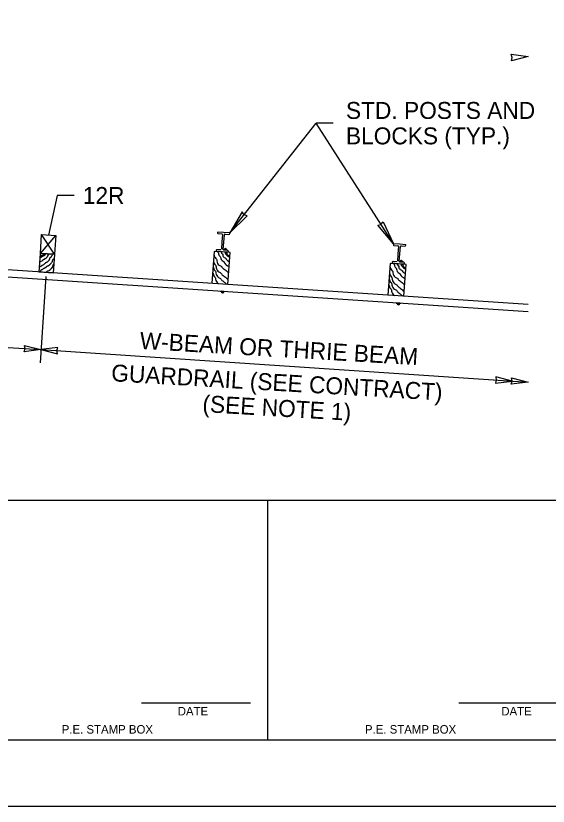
# Model space of a CAD drawing. Extents: x 1312564.2 to 1312581.5, y 1207298.4 to 1207352.6.
# Drawn here: x 1312573.115 to 1312575.615, y 1207298.421 to 1207302.136 of the extents above; entities that cross this region are included whole.
import ezdxf

# ---------------------------------------------------------------- set-up
doc = ezdxf.new("R2010")
doc.units = 0
for name, color, linetype in [('Level 1', 7, 'Continuous'), ('Level 10', 7, 'Continuous'), ('Level 13', 7, 'Continuous'), ('Level 14', 7, 'Continuous'), ('Level 15', 7, 'Continuous'), ('Level 2', 7, 'Continuous'), ('Level 20', 7, 'Continuous'), ('Level 3', 7, 'Continuous'), ('Level 36', 7, 'Continuous'), ('Level 9', 7, 'Continuous'), ('SH_GI_SheetTextInCells', 7, 'Continuous')]:
    doc.layers.add(name, color=color, linetype=linetype)

msp = doc.modelspace()

# ---------------------------------------------------------------- linework, layer by layer
at = {"layer": 'Level 1'}
for p, q in [((1312565.4154872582, 1207299.8593171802), (1312581.1654872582, 1207299.8593171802)), ((1312574.2982728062, 1207298.7334171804), (1312574.2982728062, 1207299.8593171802)), ((1312573.7057800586, 1207298.9067231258), (1312574.2175066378, 1207298.9067231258)), ((1312575.1952105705, 1207298.9067231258), (1312575.7069371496, 1207298.9067231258)), ((1312565.4154872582, 1207298.7334171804), (1312581.1654872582, 1207298.7334171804))]:
    msp.add_line(p, q, dxfattribs=at)
at = {"layer": 'Level 10'}
for p, q in [((1312574.0461583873, 1207301.0279184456), (1312574.0358822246, 1207300.8786255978)), ((1312574.1207275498, 1207301.022785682), (1312574.0461583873, 1207301.0279184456)), ((1312574.1104556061, 1207300.873554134), (1312574.1207275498, 1207301.022785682)), ((1312574.8727631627, 1207300.9721786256), (1312574.862487, 1207300.8228857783)), ((1312574.9473323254, 1207300.9670458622), (1312574.8727631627, 1207300.9721786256)), ((1312574.9370603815, 1207300.8178143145), (1312574.9473323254, 1207300.9670458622))]:
    msp.add_line(p, q, dxfattribs=at)
at = {"layer": 'Level 13'}
for points in [[(1312573.294965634, 1207300.9975759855), (1312573.2905538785, 1207300.9911023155), (1312573.2898937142, 1207300.9904370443), (1312573.2890815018, 1207300.9899128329), (1312573.2882636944, 1207300.9893941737), (1312573.2875867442, 1207300.9887455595), (1312573.2870264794, 1207300.9878017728), (1312573.2866269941, 1207300.9867753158), (1312573.2861106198, 1207300.9845726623), (1312573.2856381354, 1207300.982334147), (1312573.2850722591, 1207300.980749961), (1312573.2848100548, 1207300.9802563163), (1312573.2817499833, 1207300.9753688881), (1312573.2783825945, 1207300.97070553), (1312573.2746248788, 1207300.9663347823), (1312573.2725737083, 1207300.964280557), (1312573.271500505, 1207300.9632899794), (1312573.2703938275, 1207300.9623251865), (1312573.268983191, 1207300.9613166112), (1312573.267453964, 1207300.9605123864), (1312573.264204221, 1207300.95925536), (1312573.2609735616, 1207300.9580308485), (1312573.258760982, 1207300.9568190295), (1312573.258090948, 1207300.9563155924), (1312573.257372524, 1207300.9555539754), (1312573.256746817, 1207300.954677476), (1312573.256101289, 1207300.9538213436), (1312573.2553234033, 1207300.9531208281), (1312573.2515998, 1207300.9508374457), (1312573.2477912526, 1207300.9486758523), (1312573.243992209, 1207300.946494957), (1312573.2402971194, 1207300.9441536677), (1312573.2246592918, 1207300.933465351)], [(1312573.2881720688, 1207301.0155702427), (1312573.2850821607, 1207301.010632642), (1312573.2832165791, 1207301.0077283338), (1312573.2812929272, 1207301.0048604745), (1312573.2793293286, 1207301.0020213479), (1312573.2773439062, 1207300.9992032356), (1312573.2770386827, 1207300.9988782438), (1312573.276663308, 1207300.9986283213), (1312573.2757935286, 1207300.9982558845), (1312573.274917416, 1207300.9978903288), (1312573.2742178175, 1207300.9973360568), (1312573.273876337, 1207300.9968408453), (1312573.273586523, 1207300.9963166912), (1312573.2731335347, 1207300.99519701), (1312573.2725355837, 1207300.9927803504), (1312573.2719701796, 1207300.9903333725), (1312573.271294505, 1207300.988627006), (1312573.270983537, 1207300.9881033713), (1312573.2692403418, 1207300.9856209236), (1312573.2673483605, 1207300.9832459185), (1312573.2652962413, 1207300.9809995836), (1312573.2630726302, 1207300.978903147), (1312573.2619236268, 1207300.9780602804), (1312573.2606661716, 1207300.9773805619), (1312573.257977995, 1207300.9762955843), (1312573.255312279, 1207300.9752182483), (1312573.2540829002, 1207300.9745480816), (1312573.2529732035, 1207300.9737185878), (1312573.252551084, 1207300.9731301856), (1312573.2522583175, 1207300.97241918), (1312573.2519457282, 1207300.9717281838), (1312573.2514641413, 1207300.9711998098), (1312573.2254588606, 1207300.954328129)], [(1312573.271339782, 1207301.0166923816), (1312573.26698964, 1207301.0104177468), (1312573.2667558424, 1207301.010198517), (1312573.2664523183, 1207301.010072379), (1312573.2657273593, 1207301.0099770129), (1312573.2649972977, 1207301.00988692), (1312573.2644446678, 1207301.0095573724), (1312573.2642876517, 1207301.0093235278), (1312573.2641576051, 1207301.0090755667), (1312573.2639637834, 1207301.0085448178), (1312573.2637387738, 1207301.0073966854), (1312573.2635354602, 1207301.006233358), (1312573.2633687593, 1207301.0056836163), (1312573.2631196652, 1207301.00517522), (1312573.262226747, 1207301.0037588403), (1312573.2613062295, 1207301.0023544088), (1312573.2593449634, 1207300.9996178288), (1312573.2559621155, 1207300.9958303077), (1312573.2553318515, 1207300.9952506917), (1312573.254679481, 1207300.994688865), (1312573.2537698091, 1207300.9940598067), (1312573.2527804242, 1207300.9935745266), (1312573.2506736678, 1207300.9928508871), (1312573.2485815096, 1207300.9921491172), (1312573.2471556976, 1207300.9914152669), (1312573.2469376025, 1207300.9912630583), (1312573.2467262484, 1207300.991100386), (1312573.2461523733, 1207300.990479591), (1312573.2456614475, 1207300.9897548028), (1312573.2451487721, 1207300.989054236), (1312573.244509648, 1207300.9885061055), (1312573.2287262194, 1207300.9793180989)], [(1312573.254547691, 1207301.017811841), (1312573.252999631, 1207301.0155755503), (1312573.2526560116, 1207301.0150633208), (1312573.252320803, 1207301.014537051), (1312573.2503211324, 1207301.0113080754), (1312573.2487829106, 1207301.009380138), (1312573.2468605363, 1207301.0079299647), (1312573.2404865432, 1207301.0046332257), (1312573.2298765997, 1207300.999145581)], [(1312573.2465920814, 1207301.0183422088), (1312573.246208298, 1207301.0165880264), (1312573.245782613, 1207301.0148723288), (1312573.2451952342, 1207301.013305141), (1312573.244803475, 1207301.0126116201), (1312573.2445765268, 1207301.0122933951), (1312573.2444544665, 1207301.0121421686), (1312573.2443911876, 1207301.0120686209), (1312573.244358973, 1207301.012032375), (1312573.2443427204, 1207301.0120143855), (1312573.2443263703, 1207301.0119964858), (1312573.244022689, 1207301.0116833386), (1312573.2437021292, 1207301.0113856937), (1312573.2430136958, 1207301.0108338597), (1312573.2414708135, 1207301.0098826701), (1312573.2379069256, 1207301.0084194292), (1312573.2340597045, 1207301.007216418), (1312573.2321626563, 1207301.0065905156), (1312573.2303541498, 1207301.0058832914)], [(1312574.0452736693, 1207301.0139623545), (1312574.054231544, 1207300.9953336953), (1312574.056853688, 1207300.9925982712), (1312574.0584599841, 1207300.9838120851), (1312574.0703259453, 1207300.9641003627), (1312574.0817058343, 1207300.9564862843), (1312574.0840171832, 1207300.9529474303), (1312574.097696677, 1207300.9420354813), (1312574.1139354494, 1207300.9273606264)], [(1312574.0627443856, 1207301.0271727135), (1312574.0660285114, 1207301.0198945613), (1312574.0721544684, 1207301.007525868), (1312574.0750001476, 1207301.0052541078), (1312574.076959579, 1207300.9956695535), (1312574.0835572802, 1207300.9854863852), (1312574.092865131, 1207300.978987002), (1312574.0940206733, 1207300.9762876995), (1312574.1159994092, 1207300.9573459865)], [(1312574.079456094, 1207301.0260224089), (1312574.0839267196, 1207301.01724133), (1312574.0863323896, 1207301.016045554), (1312574.087054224, 1207301.0115247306), (1312574.0940028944, 1207300.9999957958), (1312574.1013994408, 1207300.9953673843), (1312574.103245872, 1207300.9924978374), (1312574.1176458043, 1207300.981264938)], [(1312574.0962106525, 1207301.0249392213), (1312574.098484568, 1207301.0204650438), (1312574.1035363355, 1207301.0120612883), (1312574.1094074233, 1207301.0079349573), (1312574.1191802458, 1207301.0010663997)], [(1312574.1049683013, 1207301.0241128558), (1312574.1065958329, 1207301.0157488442), (1312574.1196158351, 1207301.0078069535)], [(1312573.293034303, 1207300.9686056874), (1312573.2923153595, 1207300.9675564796), (1312573.2920134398, 1207300.9671975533), (1312573.2916553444, 1207300.966890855), (1312573.2908435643, 1207300.9663664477), (1312573.290025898, 1207300.9658478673), (1312573.289660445, 1207300.965548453), (1312573.289348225, 1207300.9651997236), (1312573.2887867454, 1207300.964256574), (1312573.28838669, 1207300.9632304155), (1312573.2878705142, 1207300.961027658), (1312573.2873990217, 1207300.9587886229), (1312573.2870548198, 1207300.957717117), (1312573.2865715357, 1207300.9567104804), (1312573.285830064, 1207300.9554718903), (1312573.2850720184, 1207300.9542450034), (1312573.2801193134, 1207300.947177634), (1312573.2763585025, 1207300.9428091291), (1312573.2743162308, 1207300.9407484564), (1312573.2732511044, 1207300.9397520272), (1312573.2721553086, 1207300.9387793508), (1312573.2707337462, 1207300.9377896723), (1312573.2691558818, 1207300.9370473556), (1312573.2657773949, 1207300.9359463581), (1312573.2625121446, 1207300.934759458), (1312573.2610758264, 1207300.9339097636), (1312573.2598524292, 1207300.9327697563), (1312573.2586584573, 1207300.9312660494)], [(1312574.0430914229, 1207300.9822585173), (1312574.0520492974, 1207300.9636298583), (1312574.054671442, 1207300.9608944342), (1312574.0562777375, 1207300.952108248), (1312574.0681436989, 1207300.9323965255), (1312574.0795235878, 1207300.9247824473), (1312574.0818349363, 1207300.921243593), (1312574.0955144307, 1207300.9103316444), (1312574.1117532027, 1207300.8956567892)], [(1312574.8718784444, 1207300.9582225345), (1312574.8808363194, 1207300.9395938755), (1312574.8834584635, 1207300.9368584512), (1312574.8850647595, 1207300.9280722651), (1312574.8969307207, 1207300.908360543), (1312574.9083106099, 1207300.9007464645), (1312574.9106219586, 1207300.8972076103), (1312574.9243014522, 1207300.8862956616), (1312574.9405402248, 1207300.8716208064)], [(1312574.8893491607, 1207300.9714328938), (1312574.8926332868, 1207300.9641547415), (1312574.8987592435, 1207300.951786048), (1312574.9016049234, 1207300.9495142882), (1312574.9035643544, 1207300.9399297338), (1312574.9101620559, 1207300.9297465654), (1312574.9194699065, 1207300.9232471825), (1312574.9206254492, 1207300.92054788), (1312574.9426041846, 1207300.9016061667)], [(1312574.9060608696, 1207300.9702825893), (1312574.910531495, 1207300.9615015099), (1312574.9129371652, 1207300.9603057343), (1312574.9136589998, 1207300.9557849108), (1312574.9206076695, 1207300.9442559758), (1312574.9280042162, 1207300.9396275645), (1312574.9298506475, 1207300.9367580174), (1312574.9442505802, 1207300.9255251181)], [(1312574.9228154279, 1207300.9691994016), (1312574.925089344, 1207300.9647252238), (1312574.9301411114, 1207300.9563214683), (1312574.9360121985, 1207300.9521951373), (1312574.9457850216, 1207300.94532658)], [(1312574.9315730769, 1207300.9683730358), (1312574.9332006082, 1207300.9600090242), (1312574.9462206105, 1207300.9520671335)], [(1312574.0393596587, 1207300.9280431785), (1312574.0483175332, 1207300.9094145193), (1312574.0509396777, 1207300.9066790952), (1312574.0525459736, 1207300.8978929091), (1312574.0644119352, 1207300.8781811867), (1312574.0668993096, 1207300.876105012)], [(1312574.0413271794, 1207300.9566274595), (1312574.050285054, 1207300.9379988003), (1312574.0529071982, 1207300.935263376), (1312574.054513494, 1207300.9264771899), (1312574.0663794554, 1207300.9067654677), (1312574.0777593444, 1207300.8991513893), (1312574.080070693, 1207300.8956125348), (1312574.093750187, 1207300.8847005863), (1312574.106012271, 1207300.8736194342)], [(1312574.8696961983, 1207300.9265186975), (1312574.8786540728, 1207300.9078900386), (1312574.881276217, 1207300.9051546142), (1312574.882882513, 1207300.8963684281), (1312574.8947484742, 1207300.876656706), (1312574.9061283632, 1207300.8690426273), (1312574.9084397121, 1207300.865503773), (1312574.922119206, 1207300.8545918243), (1312574.9383579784, 1207300.8399169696)], [(1312574.8679319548, 1207300.9008876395), (1312574.8768898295, 1207300.8822589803), (1312574.8795119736, 1207300.8795235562), (1312574.8811182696, 1207300.87073737), (1312574.8929842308, 1207300.8510256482), (1312574.9043641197, 1207300.8434115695), (1312574.9066754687, 1207300.8398727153), (1312574.9203549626, 1207300.8289607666), (1312574.9326170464, 1207300.8178796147)], [(1312574.8659644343, 1207300.8723033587), (1312574.874922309, 1207300.8536746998), (1312574.8775444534, 1207300.8509392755), (1312574.879150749, 1207300.8421530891), (1312574.8910167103, 1207300.822441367), (1312574.8935040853, 1207300.8203651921)]]:
    msp.add_spline(points, degree=3, dxfattribs=at)
at = {"layer": 'Level 14'}
for p, q in [((1312573.2961298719, 1207301.0150397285), (1312573.2358378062, 1207301.1077321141)), ((1312573.2299524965, 1207301.0194515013), (1312573.3020151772, 1207301.1033203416))]:
    msp.add_line(p, q, dxfattribs=at)
at = {"layer": 'Level 15'}
for p, q in [((1312574.1195112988, 1207301.115730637), (1312574.52576079, 1207301.63150807)), ((1312574.6054894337, 1207301.63150807), (1312574.52576079, 1207301.63150807)), ((1312574.8881024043, 1207301.064057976), (1312574.52576079, 1207301.63150807)), ((1312573.3097273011, 1207301.2914656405), (1312573.2689264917, 1207301.1055262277)), ((1312573.3894559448, 1207301.2914656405), (1312573.3097273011, 1207301.2914656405)), ((1312568.209466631, 1207301.2673344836), (1312575.5205605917, 1207300.7799342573)), ((1312568.207260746, 1207301.234245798), (1312575.5205605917, 1207300.7466985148)), ((1312573.2556953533, 1207300.9113811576), (1312573.2286219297, 1207300.505274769)), ((1312569.9194786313, 1207300.7877419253), (1312573.229335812, 1207300.5670875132)), ((1312573.2327276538, 1207300.5668613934), (1312575.5205605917, 1207300.4143410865))]:
    msp.add_line(p, q, dxfattribs=at)
for points in [[(1312575.5205605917, 1207301.9454720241), (1312575.4434425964, 1207301.9247595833), (1312575.446006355, 1207301.9403401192), (1312575.4413319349, 1207301.9554224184)], [(1312574.1195112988, 1207301.115730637), (1312574.2015849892, 1207301.1958929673), (1312574.1866439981, 1207301.2009628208), (1312574.1782180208, 1207301.214304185)], [(1312574.8881024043, 1207301.064057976), (1312574.81434338, 1207301.1519311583), (1312574.8297118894, 1207301.1555012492), (1312574.839413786, 1207301.1679456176)], [(1312573.2961298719, 1207301.0150397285), (1312573.2299524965, 1207301.0194515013), (1312573.2358378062, 1207301.1077321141), (1312573.3020151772, 1207301.1033203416)], [(1312573.290244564, 1207300.9267591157), (1312573.2240671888, 1207300.9311708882), (1312573.2299524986, 1207301.019451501), (1312573.2961298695, 1207301.0150397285)], [(1312573.2327276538, 1207300.5668613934), (1312573.153553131, 1207300.5564890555), (1312573.158147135, 1207300.5715960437), (1312573.1555004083, 1207300.5871626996)], [(1312573.2327276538, 1207300.5668613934), (1312573.3100367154, 1207300.5468739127), (1312573.3073267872, 1207300.5624296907), (1312573.3118593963, 1207300.5775552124)], [(1312575.4459870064, 1207300.419183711), (1312575.3687367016, 1207300.4393970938), (1312575.3714011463, 1207300.4238334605), (1312575.3668243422, 1207300.4087212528)], [(1312575.5205605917, 1207300.4143410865), (1312575.4413711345, 1207300.4040833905), (1312575.4459870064, 1207300.419183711), (1312575.4433628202, 1207300.434754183)]]:
    msp.add_lwpolyline(points, close=True, dxfattribs=at)
at = {"layer": 'Level 2'}
for p, q in [((1312574.0751190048, 1207300.8418790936), (1312574.0752393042, 1207300.8436268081)), ((1312574.0751190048, 1207300.8418790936), (1312574.096868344, 1207300.8403820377)), ((1312574.096988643, 1207300.842129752), (1312574.096868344, 1207300.8403820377)), ((1312574.9017237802, 1207300.7861392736), (1312574.9018440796, 1207300.7878869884)), ((1312574.9017237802, 1207300.7861392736), (1312574.9234731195, 1207300.7846422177)), ((1312574.9235934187, 1207300.7863899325), (1312574.9234731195, 1207300.7846422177))]:
    msp.add_line(p, q, dxfattribs=at)
msp.add_lwpolyline([(1312564.4779872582, 1207298.4209171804), (1312581.4779872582, 1207298.4209171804), (1312581.4779872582, 1207309.4209171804), (1312564.4779872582, 1207309.4209171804)], close=True, dxfattribs=at)
at = {"layer": 'Level 3'}
for p, q in [((1312574.079436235, 1207300.8378230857), (1312574.0793937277, 1207300.8372055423)), ((1312574.0919707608, 1207300.836339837), (1312574.0793937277, 1207300.8372055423)), ((1312574.0920132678, 1207300.8369573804), (1312574.079436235, 1207300.8378230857)), ((1312574.0922821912, 1207300.8406977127), (1312574.0797051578, 1207300.841563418)), ((1312574.0832480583, 1207300.8413195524), (1312574.0829852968, 1207300.837502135)), ((1312574.0886359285, 1207300.8397731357), (1312574.0831675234, 1207300.8401495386)), ((1312574.0832651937, 1207300.841401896), (1312574.083259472, 1207300.8413187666)), ((1312574.0884537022, 1207300.8371257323), (1312574.0887164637, 1207300.8409431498)), ((1312574.088727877, 1207300.8409423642), (1312574.088733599, 1207300.8410254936)), ((1312574.0920132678, 1207300.8369573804), (1312574.0919707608, 1207300.836339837)), ((1312574.9060410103, 1207300.7820832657), (1312574.9059985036, 1207300.7814657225)), ((1312574.9185755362, 1207300.780600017), (1312574.9059985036, 1207300.7814657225)), ((1312574.9186180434, 1207300.7812175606), (1312574.9060410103, 1207300.7820832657)), ((1312574.9188869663, 1207300.7849578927), (1312574.9063099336, 1207300.7858235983)), ((1312574.9098528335, 1207300.7855797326), (1312574.9095900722, 1207300.7817623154)), ((1312574.9152407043, 1207300.7840333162), (1312574.909772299, 1207300.7844097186)), ((1312574.9098699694, 1207300.7856620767), (1312574.9098642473, 1207300.785578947)), ((1312574.9150584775, 1207300.7813859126), (1312574.9153212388, 1207300.7852033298)), ((1312574.9153326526, 1207300.7852025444), (1312574.9153383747, 1207300.7852856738)), ((1312574.9186180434, 1207300.7812175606), (1312574.9185755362, 1207300.780600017))]:
    msp.add_line(p, q, dxfattribs=at)
for centre, start, end in [((1312574.0860859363, 1207300.8426375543), 219.06596139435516, 266.0624131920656), ((1312574.0860859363, 1207300.8426375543), 266.0624131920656, 313.0588649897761), ((1312574.9126907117, 1207300.7868977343), 219.06596139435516, 266.0624131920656), ((1312574.9126907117, 1207300.7868977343), 266.0624131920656, 313.0588649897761)]:
    msp.add_arc(centre, 0.008619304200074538, start, end, dxfattribs=at)
at = {"layer": 'Level 36'}
for points in [[(1312574.0969999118, 1207301.03963745), (1312574.097573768, 1207301.0399172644), (1312574.0968884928, 1207301.040590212), (1312574.0975326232, 1207301.0409312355), (1312574.0969470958, 1207301.0414506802), (1312574.0977110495, 1207301.0418661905), (1312574.0992784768, 1207301.04202814), (1312574.0974199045, 1207301.0421599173), (1312574.0977110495, 1207301.0418661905), (1312574.0974199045, 1207301.0421599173), (1312574.0977573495, 1207301.0425271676), (1312574.101182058, 1207301.0422859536), (1312574.1016454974, 1207301.041585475), (1312574.1012238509, 1207301.0412603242), (1312574.1019748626, 1207301.0408985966), (1312574.1011584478, 1207301.040332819), (1312574.097573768, 1207301.0399172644), (1312574.0968884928, 1207301.040590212), (1312574.0975326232, 1207301.0409312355), (1312574.1012238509, 1207301.0412603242), (1312574.1019748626, 1207301.0408985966), (1312574.1011584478, 1207301.040332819), (1312574.101894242, 1207301.039760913), (1312574.101090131, 1207301.039352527), (1312574.103410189, 1207301.0391867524), (1312574.1039908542, 1207301.0389441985), (1312574.1041297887, 1207301.038737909), (1312574.104271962, 1207301.0385154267), (1312574.1045553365, 1207301.0381090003), (1312574.104261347, 1207301.0339293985), (1312574.1045553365, 1207301.0381090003), (1312574.1040909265, 1207301.038763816), (1312574.1037188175, 1207301.03916765), (1312574.1029639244, 1207301.0392204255), (1312574.1026106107, 1207301.0388651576), (1312574.102259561, 1207301.0386585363), (1312574.1021028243, 1207301.0382802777), (1312574.1018088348, 1207301.0341006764), (1312574.1021028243, 1207301.0382802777), (1312574.1015976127, 1207301.038701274), (1312574.1007520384, 1207301.0389969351), (1312574.100004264, 1207301.039426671), (1312574.0994300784, 1207301.0394684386), (1312574.098417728, 1207301.0393349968), (1312574.0974144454, 1207301.0392067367), (1312574.0969481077, 1207301.038886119), (1312574.0965743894, 1207301.0386665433), (1312574.0962813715, 1207301.0344905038), (1312574.0965743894, 1207301.0386665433), (1312574.0961533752, 1207301.0392980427), (1312574.0958382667, 1207301.0395179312), (1312574.0951860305, 1207301.039764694), (1312574.0945402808, 1207301.0394317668), (1312574.094052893, 1207301.0390900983), (1312574.0938365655, 1207301.0388582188), (1312574.0935435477, 1207301.0346821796), (1312574.0938365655, 1207301.0388582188), (1312574.0939615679, 1207301.03909204), (1312574.0945402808, 1207301.0394317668), (1312574.0951860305, 1207301.039764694), (1312574.103410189, 1207301.0391867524)], [(1312574.9236046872, 1207300.98389763), (1312574.9241785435, 1207300.9841774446), (1312574.923493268, 1207300.9848503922), (1312574.9241373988, 1207300.9851914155), (1312574.9235518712, 1207300.9857108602), (1312574.9243158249, 1207300.986126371), (1312574.9258832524, 1207300.98628832), (1312574.9240246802, 1207300.9864200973), (1312574.9243158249, 1207300.986126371), (1312574.9240246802, 1207300.9864200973), (1312574.9243621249, 1207300.9867873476), (1312574.9277868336, 1207300.986546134), (1312574.9282502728, 1207300.9858456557), (1312574.9278286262, 1207300.9855205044), (1312574.9285796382, 1207300.9851587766), (1312574.9277632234, 1207300.9845929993), (1312574.9241785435, 1207300.9841774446), (1312574.923493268, 1207300.9848503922), (1312574.9241373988, 1207300.9851914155), (1312574.9278286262, 1207300.9855205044), (1312574.9285796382, 1207300.9851587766), (1312574.9277632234, 1207300.9845929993), (1312574.9284990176, 1207300.9840210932), (1312574.9276949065, 1207300.983612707), (1312574.9300149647, 1207300.9834469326), (1312574.9305956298, 1207300.9832043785), (1312574.9307345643, 1207300.982998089), (1312574.9308767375, 1207300.982775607), (1312574.9311601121, 1207300.9823691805), (1312574.9308661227, 1207300.9781895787), (1312574.9311601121, 1207300.9823691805), (1312574.930695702, 1207300.9830239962), (1312574.9303235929, 1207300.9834278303), (1312574.9295686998, 1207300.983480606), (1312574.9292153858, 1207300.9831253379), (1312574.9288643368, 1207300.9829187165), (1312574.9287075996, 1207300.9825404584), (1312574.9284136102, 1207300.9783608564), (1312574.9287075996, 1207300.9825404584), (1312574.9282023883, 1207300.982961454), (1312574.9273568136, 1207300.9832571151), (1312574.926609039, 1207300.9836868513), (1312574.9260348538, 1207300.9837286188), (1312574.9250225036, 1207300.9835951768), (1312574.924019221, 1207300.9834669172), (1312574.9235528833, 1207300.9831462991), (1312574.9231791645, 1207300.9829267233), (1312574.9228861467, 1207300.978750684), (1312574.9231791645, 1207300.9829267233), (1312574.9227581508, 1207300.9835582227), (1312574.9224430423, 1207300.9837781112), (1312574.921790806, 1207300.9840248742), (1312574.9211450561, 1207300.983691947), (1312574.9206576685, 1207300.9833502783), (1312574.920441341, 1207300.9831183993), (1312574.920148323, 1207300.9789423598), (1312574.920441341, 1207300.9831183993), (1312574.920566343, 1207300.9833522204), (1312574.9211450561, 1207300.983691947), (1312574.921790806, 1207300.9840248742), (1312574.9300149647, 1207300.9834469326)]]:
    msp.add_lwpolyline(points, dxfattribs=at)
at = {"layer": 'Level 9'}
for p, q in [((1312574.0854437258, 1207301.1076159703), (1312574.0830292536, 1207301.073176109)), ((1312574.0916852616, 1207301.0725692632), (1312574.0940997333, 1207301.1070091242)), ((1312574.0830292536, 1207301.073176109), (1312574.0806122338, 1207301.0387364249)), ((1312574.0892682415, 1207301.0381295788), (1312574.0916852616, 1207301.0725692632)), ((1312574.9120485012, 1207301.0518761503), (1312574.9096340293, 1207301.0174362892)), ((1312574.918290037, 1207301.0168294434), (1312574.9207045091, 1207301.0512693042)), ((1312574.9096340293, 1207301.0174362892), (1312574.9072170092, 1207300.9829966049)), ((1312574.9158730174, 1207300.982389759), (1312574.918290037, 1207301.0168294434))]:
    msp.add_line(p, q, dxfattribs=at)
for points in [[(1312574.0905044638, 1207301.1177642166), (1312574.0614976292, 1207301.1197977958), (1312574.0613071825, 1207301.117081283)], [(1312574.0654173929, 1207301.1123513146), (1312574.0823610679, 1207301.111163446)], [(1312574.1193208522, 1207301.1130141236), (1312574.1195112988, 1207301.115730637), (1312574.0905044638, 1207301.1177642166)], [(1312574.0976472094, 1207301.1100917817), (1312574.1145908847, 1207301.1089039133)], [(1312574.055392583, 1207301.0327297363), (1312574.0552032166, 1207301.0300147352), (1312574.0842100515, 1207301.0279811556)], [(1312574.0770647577, 1207301.0356537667), (1312574.060122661, 1207301.036841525)], [(1312574.1092961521, 1207301.0333941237), (1312574.0923508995, 1207301.034582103)], [(1312574.9171092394, 1207301.0620243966), (1312574.8881024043, 1207301.064057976), (1312574.8879119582, 1207301.061341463)], [(1312574.8920221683, 1207301.0566114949), (1312574.9089658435, 1207301.0554236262)], [(1312574.9459256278, 1207301.057274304), (1312574.9461160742, 1207301.059990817), (1312574.9171092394, 1207301.0620243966)], [(1312574.924251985, 1207301.0543519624), (1312574.94119566, 1207301.0531640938)], [(1312574.0842100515, 1207301.0279811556), (1312574.1132168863, 1207301.0259475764), (1312574.1134064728, 1207301.0286657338)], [(1312574.8819973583, 1207300.9769899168), (1312574.881807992, 1207300.9742749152), (1312574.9108148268, 1207300.9722413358)], [(1312574.9036695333, 1207300.9799139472), (1312574.8867274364, 1207300.981101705)], [(1312574.9108148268, 1207300.9722413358), (1312574.939821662, 1207300.9702077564), (1312574.940011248, 1207300.9729259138)], [(1312574.9359009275, 1207300.977654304), (1312574.918955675, 1207300.978842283)]]:
    msp.add_lwpolyline(points, dxfattribs=at)
for centre, radius, start, end in [((1312574.0657272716, 1207301.1167714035), 0.004430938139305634, 175.9897308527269, 265.9897320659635), ((1312574.082128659, 1207301.1078483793), 0.0033232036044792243, 355.989731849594, 85.98973184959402), ((1312574.0974148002, 1207301.106776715), 0.0033232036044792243, 85.98973184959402, 175.98973184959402), ((1312574.1149007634, 1207301.1133240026), 0.004430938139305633, 265.98973183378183, 355.9897310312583), ((1312574.0598127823, 1207301.0324214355), 0.004430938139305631, 85.98973176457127, 176.01018654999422), ((1312574.0925833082, 1207301.0378971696), 0.0033232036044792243, 175.98973184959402, 265.989731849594), ((1312574.1089862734, 1207301.0289740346), 0.00443093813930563, 356.01018653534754, 85.98973183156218), ((1312574.892332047, 1207301.0610315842), 0.004430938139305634, 175.9897308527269, 265.9897320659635), ((1312574.9087334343, 1207301.0521085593), 0.0033232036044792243, 355.989731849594, 85.98973184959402), ((1312574.9240195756, 1207301.0510368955), 0.0033232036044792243, 85.98973184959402, 175.98973184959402), ((1312574.9415055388, 1207301.0575841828), 0.004430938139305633, 265.98973183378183, 355.9897310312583), ((1312574.8864175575, 1207300.9766816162), 0.004430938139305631, 85.98973176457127, 176.01018654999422), ((1312574.9191880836, 1207300.98215735), 0.0033232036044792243, 175.98973184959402, 265.989731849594), ((1312574.9355910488, 1207300.9732342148), 0.00443093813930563, 356.01018653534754, 85.98973183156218)]:
    msp.add_arc(centre, radius, start, end, dxfattribs=at)

# ---------------------------------------------------------------- texts
at = {"layer": 'Level 20'}
for s, p in [('STD. POSTS AND ', (1312574.6652859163, 1207301.6514402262)), ('BLOCKS (TYP.)', (1312574.6652859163, 1207301.5318472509)), ('12R', (1312573.4293202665, 1207301.251601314))]:
    msp.add_text(s, height=0.07972865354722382, dxfattribs=at).set_placement(p)
for s, p in [('W-BEAM OR THRIE BEAM ', (1312573.695003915, 1207300.5706573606)), ('GUARDRAIL (SEE CONTRACT) ', (1312573.561226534, 1207300.4188037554)), ('(SEE NOTE 1)', (1312573.98961197, 1207300.2737865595))]:
    msp.add_text(s, height=0.07972865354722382, rotation=356.6311333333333, dxfattribs=at).set_placement(p)
at = {"layer": 'SH_GI_SheetTextInCells'}
for s, p in [('DATE', (1312573.8752164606, 1207298.8474932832)), ('DATE', (1312575.3949212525, 1207298.8474932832)), ('P.E. STAMP BOX', (1312573.3305246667, 1207298.7620150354)), ('P.E. STAMP BOX', (1312574.7544979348, 1207298.7620150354))]:
    msp.add_text(s, height=0.04003199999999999, dxfattribs=at).set_placement(p)

doc.saveas('drawing.dxf')
